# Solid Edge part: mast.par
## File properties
Author: Administrator
Template: Normal.par
Last saved by: Administrator
Revision: 4
Application: Solid Edge
Accuracy: 0,990
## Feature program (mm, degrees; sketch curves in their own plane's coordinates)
sketch for "unnamed Protrusion 1" plane through (0, 0, 0) normal (0, 0, 1) x-axis (1, 0, 0)
  circle centre (0, 0) radius 5
extrude "unnamed Protrusion 1" add finite 600 along +normal
sketch for "ExtrudedProtrusion_2" plane through (0, 0, 0) normal (1, 0, 0) x-axis (0, 1, 0)
  circle centre (0, 200) radius 2.5
extrude "ExtrudedProtrusion_2" add finite 225 along -normal
fillet "Round_1" radius 5
fillet "Round_2" radius 2.5
sketch for "ExtrudedProtrusion_3" plane through (0, 0, 0) normal (0, -1, 0) x-axis (1, 0, 0)
  line (-212.5, 207.5) -> (-10, 585)
  line (-10, 585) -> (-10, 207.5)
  line (-212.5, 207.5) -> (-10, 207.5)
extrude "ExtrudedProtrusion_3" add finite 0.5 symmetric
swept cutout "unnamed SweptCutout 1"
swept protrusion "unnamed SweptProtrusion 1"
swept protrusion "unnamed SweptProtrusion 2"
swept protrusion "unnamed SweptProtrusion 3"
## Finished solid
Body 1: solid body, 23 faces, 38 edges, 16 vertices.
  Faces by surface: cylinder 11, plane 7, sphere 2, spline 2, torus 1
  Edges by curve: line 15, circle 14, intersection 5, ellipse 4
Bounding box of the edges (mm; curved faces can reach further): 227.500 x 10.000 x 595.000, from (-222.5, -5, 0) to (5, 5, 595).
Cylindrical faces by radius (mm): R0.25 x6, R0.5 x3, R2.5 x1, R5 x1
Toroidal faces (ring radius, tube radius in mm): R3.5 r0.25 x1
Spherical faces by radius (mm): R2.5 x1, R5 x1
Planar faces by outward normal: +y 1, +z 2, -x 1, -y 1, -z 1, oblique 1
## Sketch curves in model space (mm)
circle centre (-2.2024, 0, 590) radius 0.25
line (-6.5, 0, 590) -> (-2.2024, 0, 590)
arc centre (-6.5, 0, 586.5) radius 3.5 from (-10, 0, 586.5) through (-8.9018, 0, 589.0458) to (-6.5, 0, 590)
line (-10, 0, 586.5) -> (-10, 0, 207.5)
circle centre (-7, 0, 201.628) radius 0.25
line (-7, 0, 201.62) -> (-7, 0, 205.5)
arc centre (-9, 0, 205.5) radius 2 from (-9, 0, 207.5) through (-7.5453, 0, 206.8725) to (-7, 0, 205.5)
line (-214.5, 0, 205.5037) -> (-214.5, 0, 200.3215)
arc centre (-212.5037, 0, 205.5037) radius 1.9963 from (-214.5, 0, 205.5037) through (-213.8737, 0, 206.9558) to (-212.5037, 0, 207.5)
line (-212.5037, 0, 207.5) -> (-9, 0, 207.5)
line (-10, 0, 584.192) -> (-10, 0, 207.5)
line (-212.0654, 0, 207.5) -> (-10, 0, 207.5)
circle centre (-10, 0, 300) radius 0.25
circle centre (-10, 0, 300) radius 0.5
line (-10, 9.3489, 300) -> (-10, -19.6224, 300)
line (-10, 0, 585) -> (-10, 0, 207.5)
line (-212.5, 0, 207.5) -> (-10, 0, 585)
line (-212.5, 0, 207.5) -> (-10, 0, 207.5)
circle centre (0, 0, 200) radius 2.5
line (0, 0, 256.3844) -> (0, 0, 238.2255)
line (0, -26.259, 200) -> (0, 32.1766, 200)
circle centre (0, 0, 0) radius 5
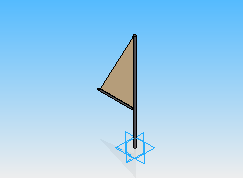
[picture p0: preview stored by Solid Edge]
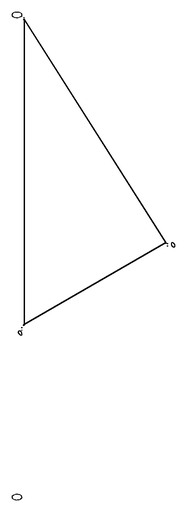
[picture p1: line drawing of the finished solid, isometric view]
